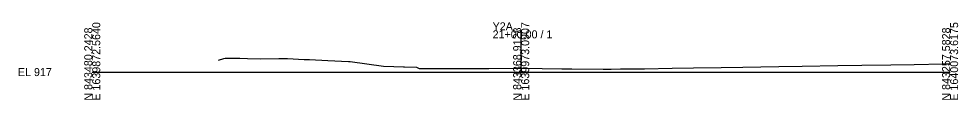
# Model space of a CAD drawing. Extents: x -26 to 303, y -10 to 10517.
# Drawn here: x -25.7 to 302.8, y 10490.3 to 10517.5 of the extents above; entities that cross this region are included whole.
import ezdxf

# ---------------------------------------------------------------- set-up
doc = ezdxf.new("R2010")
doc.units = 0
for name, color, linetype in [('Exist Cross Section Cell', 7, 'Continuous'), ('Exist XS Center Line Elevation Label', 7, 'Continuous'), ('Exist XS Ground Line', 7, 'Continuous')]:
    doc.layers.add(name, color=color, linetype=linetype)

msp = doc.modelspace()

# ---------------------------------------------------------------- linework, layer by layer
at = {"layer": 'Exist Cross Section Cell'}
for p, q in [((150, 10500), (150, 10514.61)), ((0, 10500), (150, 10500)), ((150, 10500), (300, 10500))]:
    msp.add_line(p, q, dxfattribs=at)
at = {"layer": 'Exist XS Ground Line'}
msp.add_lwpolyline([(44.19, 10504.2), (46.01, 10504.81), (46.46, 10504.85), (48.03, 10504.82), (51.61, 10504.87), (54.25, 10504.8), (58.73, 10504.59), (65.24, 10504.79), (66.69, 10504.8), (68.24, 10504.72), (74.13, 10504.43), (75.96, 10504.38), (82.35, 10504.03), (89.58, 10503.75), (90.14, 10503.7), (101.88, 10502.04), (105.41, 10501.91), (108.87, 10501.79), (109.24, 10501.78), (113.39, 10501.74), (114.31, 10501.25), (115.95, 10501.28), (117.38, 10501.3), (124.94, 10501.24), (125.48, 10501.24), (133.22, 10501.26), (138.72, 10501.27), (150, 10501.32), (150.48, 10501.32), (164.22, 10501.19), (166.1, 10501.18), (167.72, 10501.18), (178.69, 10501.03), (181.51, 10501.05), (184.71, 10501.08), (188.83, 10501.14), (193.08, 10501.19), (202.75, 10501.33), (210.31, 10501.44), (219.96, 10501.58), (227.49, 10501.7), (240.15, 10501.91), (248.31, 10502.04), (260.73, 10502.25), (269.08, 10502.39), (279.24, 10502.56), (287.41, 10502.69), (297.55, 10502.85), (300, 10502.88)], dxfattribs=at)

# ---------------------------------------------------------------- texts
at = {"layer": 'Exist Cross Section Cell'}
for s, p in [('E 1639872.5640', (2.8, 10490)), ('E 1639973.0907', (152.8, 10490)), ('E 1640073.6175', (302.8, 10490)), ('N 843480.2428', (0, 10490)), ('N 843368.9128', (150, 10490)), ('N 843257.5828', (300, 10490))]:
    msp.add_text(s, height=2.8, rotation=90, dxfattribs=at).set_placement(p)
for s, p in [('Y2A', (140, 10514.61)), ('21+00.00 / 1', (140, 10511.81)), ('EL 917', (-26, 10498.6))]:
    msp.add_text(s, height=2.8, dxfattribs=at).set_placement(p)
at = {"layer": 'Exist XS Center Line Elevation Label'}
msp.add_text('918.32', height=1, dxfattribs=at).set_placement((147.96, 10499.2))

doc.saveas('drawing.dxf')
